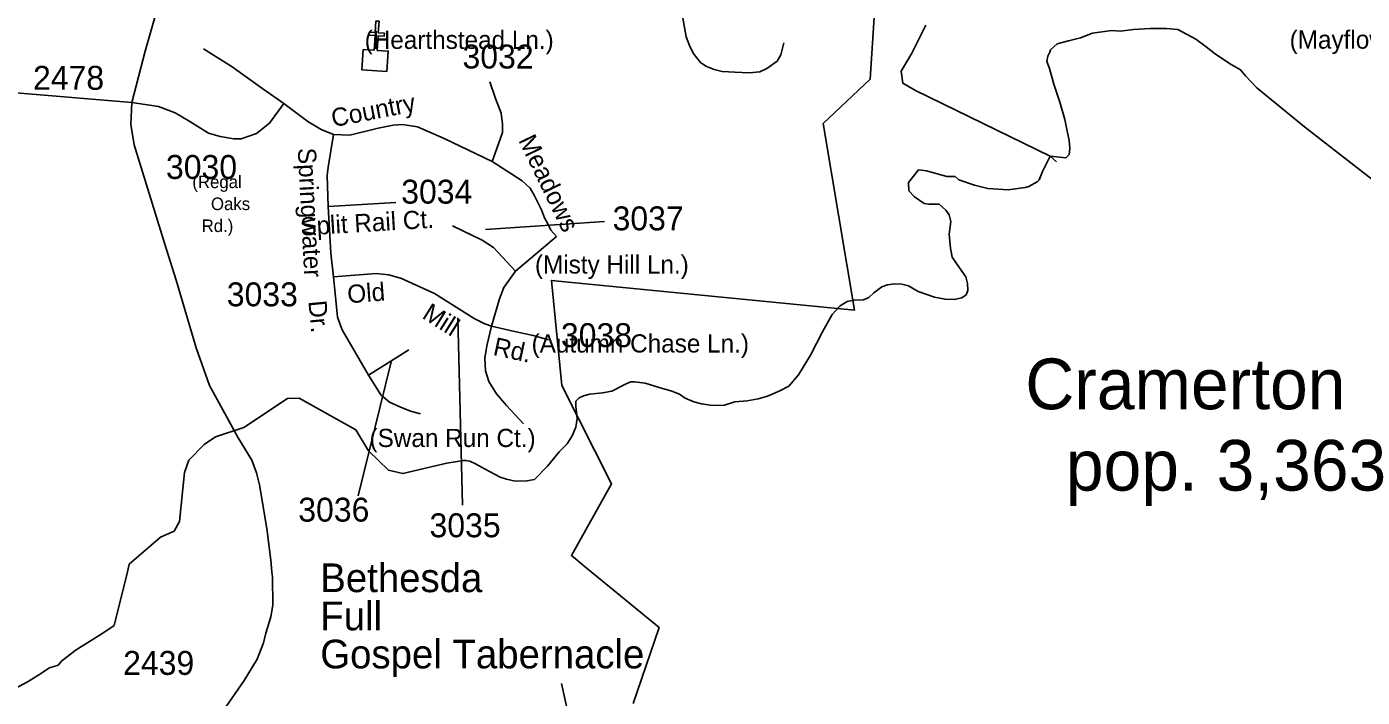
# Model space of a CAD drawing. Extents: x 1364363 to 1407445, y 538563 to 573342.
# Drawn here: x 1372368 to 1379352, y 544821 to 548325 of the extents above; entities that cross this region are included whole.
import ezdxf

# ---------------------------------------------------------------- set-up
doc = ezdxf.new("R2010")
doc.units = 0
for name, color, linetype in [('Exist Boundary Political City Limit New', 7, 'Continuous'), ('Exist Civil Demographics City Label', 7, 'Continuous'), ('Exist Cultural Church CELL', 7, 'Continuous'), ('Exist Cultural Church Label', 7, 'Continuous'), ('Exist Hydrographic Creek Single Shore', 7, 'Continuous'), ('Exist Road Secondary Type 51 Attributed', 7, 'Continuous'), ('Exist Road Secondary Type 51 Label', 7, 'Continuous'), ('Exist Road Secondary Type 51 Number Label', 7, 'Continuous')]:
    doc.layers.add(name, color=color, linetype=linetype)

msp = doc.modelspace()

# ---------------------------------------------------------------- linework, layer by layer
at = {"layer": 'Exist Boundary Political City Limit New'}
msp.add_lwpolyline([(1376807.4, 548482.4), (1376778.2, 548050.8), (1376533.5, 547819.8), (1376697.4, 546843.8), (1375111.8, 546998.8), (1375167.4, 546450.8), (1375426.8, 545936.9), (1375217, 545561.1), (1375280.8, 545506.7), (1375675.1, 545185.3), (1375539.5, 544787.6)], dxfattribs=at)
at = {"layer": 'Exist Cultural Church CELL'}
msp.add_lwpolyline([(1374128.3, 548205.9), (1374185.1, 548202.4), (1374189.9, 548278.4), (1374158, 548280.5), (1374159, 548296.4), (1374190.9, 548294.4), (1374194.7, 548354.4), (1374210.7, 548353.4), (1374206.9, 548293.4), (1374238.8, 548291.4), (1374237.8, 548275.4), (1374205.9, 548277.4), (1374201.1, 548201.4), (1374258.6, 548197.7), (1374251.9, 548091.4), (1374121.6, 548099.7)], close=True, dxfattribs=at)
at = {"layer": 'Exist Hydrographic Creek Single Shore'}
for points in [[(1377720.4, 547647.7), (1377016.1, 547992.2), (1376950.5, 548029.3), (1376941.7, 548093.3), (1376997.2, 548187.2), (1377069.7, 548332.3)], [(1378801.7, 548006), (1378741.9, 548068.8), (1378716.3, 548100.5), (1378666.9, 548127.7), (1378584, 548181.9), (1378536.8, 548220.6), (1378481.6, 548259.5), (1378388.5, 548309.8), (1378326.7, 548315.1), (1378242.5, 548315.2), (1378156.4, 548310.3), (1378086.2, 548301.9), (1378041.2, 548304.7), (1377941.4, 548290.5), (1377878.7, 548267.6), (1377815.9, 548250.5), (1377756, 548236.3), (1377721.8, 548204.9), (1377717.8, 548192), (1377707.3, 548171.7), (1377702.7, 548143.9), (1377716, 548105.9), (1377740.2, 548025), (1377770.4, 547930.8), (1377796.5, 547840), (1377807.5, 547787.3), (1377820.3, 547731.2), (1377823.3, 547689.3), (1377818.7, 547657.4), (1377802.4, 547639.7), (1377720.4, 547647.7), (1377753.9, 547618.5)], [(1380434.5, 545971.1), (1380301.8, 546214), (1380129.4, 546443.2), (1380115.2, 546511.7), (1380004, 546760), (1380006.8, 547065.3), (1379949.8, 547128.1), (1379895.6, 547145.2), (1379050.8, 547801.7), (1378801.7, 548006)], [(1377720.4, 547647.7), (1377680.5, 547567.8), (1377663.3, 547525), (1377666.2, 547527.9), (1377651.9, 547513.6), (1377609.2, 547490.8), (1377589, 547483.9), (1377500.6, 547471.8), (1377394.8, 547479.6), (1377325.2, 547497.5), (1377241.8, 547525.4), (1377223.2, 547542.7), (1377180.6, 547542.7), (1377073.9, 547572.6), (1377031.3, 547576.9), (1376979, 547511.5), (1376981.8, 547467.9), (1377010, 547436), (1377061.1, 547401.9), (1377086.7, 547397.6), (1377139, 547397), (1377174.4, 547366.7), (1377191.8, 547341.7), (1377201, 547306.3), (1377191.8, 547241.7), (1377198.2, 547167.6), (1377207.3, 547121.5), (1377230.6, 547087.4), (1377257.7, 547046.7), (1377279.2, 547018.3), (1377288.4, 546983.7), (1377289.6, 546945.9), (1377281.2, 546923.9), (1377258.9, 546908.8), (1377218.7, 546899.7), (1377170.7, 546900.7), (1377114.8, 546911.7), (1377029.4, 546941.3), (1376980, 546970.2), (1376944.2, 546979.1), (1376906.2, 546981.5), (1376870.1, 546976.5), (1376839.8, 546965.6), (1376797.3, 546934.5), (1376772.7, 546910.4), (1376744.4, 546897), (1376694.4, 546896.4), (1376658.2, 546888.9), (1376621.7, 546865.8), (1376580.8, 546820.6), (1376528.8, 546729.8), (1376466.2, 546608.8), (1376404.1, 546505.8), (1376352.8, 546446.9), (1376306.3, 546421.6), (1376241.7, 546393.4), (1376193.4, 546380.4), (1376135.1, 546369.3), (1376071, 546364.8), (1376016.7, 546347.8), (1375954.5, 546345), (1375896.7, 546354.4), (1375856.9, 546365), (1375811.3, 546384)], [(1375811.3, 546384), (1375781.7, 546405.1), (1375742, 546419.9), (1375676.4, 546439.2), (1375602.8, 546462.9), (1375547, 546469.7), (1375524.8, 546468.6), (1375492.6, 546452.8), (1375427.9, 546420.4), (1375379.6, 546411.6), (1375313.5, 546404.7), (1375279.3, 546395.5), (1375257.1, 546386.1), (1375240.6, 546368.4), (1375240.1, 546339.7), (1375246.8, 546278), (1375239.8, 546232.2), (1375220.9, 546186.6), (1375194, 546145.3), (1375153.2, 546103.5), (1375091.6, 546029.2), (1375024.1, 545958.3)], [(1372552.7, 545010.3), (1372626.8, 545068.1), (1372766.5, 545156.5), (1372826.4, 545196.5), (1372894.8, 545476.1), (1372903.4, 545516.1), (1373067.4, 545657.3), (1373138.7, 545688.7), (1373167.2, 545740.1), (1373192.9, 545996.1), (1373215.7, 546059.7), (1373295.5, 546142.5), (1373355.4, 546182.4), (1373503.7, 546230.9), (1373731.8, 546382.2), (1373793.9, 546384.4), (1374089.9, 546217.6), (1374154.9, 546108), (1374260.9, 546007.4), (1374335.9, 545989.5), (1374564.8, 546043.7), (1374651.8, 546057.7)], [(1375024.1, 545958.3), (1374983.9, 545951), (1374921.9, 545950.6), (1374878, 545959.7), (1374844.2, 545971.8), (1374765, 546013.6), (1374715.6, 546040.9), (1374685.9, 546055.4), (1374663.9, 546057.5), (1374651.8, 546057.7)], [(1372552.7, 545010.3), (1372532.7, 544988.2), (1372487, 544973.9), (1372427.2, 544934), (1372404.3, 544919.7), (1372375.8, 544902.6), (1372284.6, 544854.1)]]:
    msp.add_lwpolyline(points, dxfattribs=at)
at = {"layer": 'Exist Road Secondary Type 51 Attributed'}
for p, q in [((1373945.5, 547385.7), (1374297.7, 547406.8)), ((1374155, 546503.9), (1374366, 546636.3)), ((1375203.1, 544717.6), (1375164.3, 544893.3))]:
    msp.add_line(p, q, dxfattribs=at)
for points in [[(1372917.5, 547929), (1372988.4, 548197.4), (1373112.8, 548637.2), (1373145.3, 548760.6), (1373170.2, 548865.1), (1373194.1, 548979.6), (1373260.6, 549189.9), (1373301.9, 549365.5), (1373340.5, 549476.4), (1373359.1, 549532.3), (1373423, 549729.3), (1373473.5, 549846.5), (1373522.1, 549906.9)], [(1375785, 548447.6), (1375816.8, 548272.3), (1375833.9, 548227.1), (1375854, 548186.5), (1375891.3, 548138.3), (1375919.2, 548118.8), (1375962.6, 548100.7), (1376004.5, 548091.7), (1376071.3, 548087.2), (1376145.7, 548084.1), (1376201.6, 548088.7), (1376238.8, 548106.7), (1376293.1, 548145.8), (1376311.8, 548177.4), (1376327.3, 548240.7)], [(1373712, 547923), (1373603.4, 548001.2), (1373442, 548115.6), (1373293, 548208.9)], [(1374802, 547620.5), (1374835.4, 547712.4), (1374855.6, 547772.5), (1374855.6, 547816.2), (1374849.3, 547873.4), (1374819.9, 547950.1), (1374789.6, 548037.4)], [(1372313.3, 547979.5), (1372917.5, 547929)], [(1373261.2, 544568.6), (1373305.4, 544619.2), (1373505.5, 544909.1), (1373574, 545019.8), (1373605.7, 545105.2), (1373618.7, 545155), (1373645.3, 545241.3), (1373656.1, 545301.5), (1373653, 545447.5), (1373650.6, 545475.6), (1373645.3, 545537.8), (1373623.6, 545701.8), (1373585.3, 545930.5), (1373569.3, 545994.4), (1373546, 546060), (1373474.6, 546175.9), (1373324.8, 546449.7), (1373255, 546646.8), (1373149.5, 547000.5), (1373089, 547194.6), (1372930.7, 547708), (1372912, 547814.5), (1372917.5, 547929)], [(1372917.5, 547929), (1373057.2, 547907.9), (1373144.1, 547874.8), (1373221.7, 547829.7), (1373319.2, 547769.2), (1373380.4, 547750.6), (1373452.2, 547739.9), (1373489.5, 547739.9), (1373569.2, 547766.5), (1373637.5, 547820.7), (1373712, 547923)], [(1373973.4, 547762), (1373907.5, 547787.5), (1373839.2, 547829.7), (1373712, 547923)], [(1373973.4, 547762), (1373945.5, 547590.4), (1373939.3, 547548.3), (1373945.5, 547385.7)], [(1374802, 547620.5), (1374550.6, 547740.9), (1374411, 547801.1), (1374333.4, 547813.1), (1374283.8, 547810.1), (1374206.2, 547795.1), (1374057.2, 547759), (1373973.4, 547762)], [(1375138, 547227.8), (1375108.5, 547262.4), (1375093.7, 547294), (1375075.1, 547325.6), (1375059.6, 547367.7), (1375022.4, 547444.5), (1375000.6, 547480.6), (1374958.7, 547519.7), (1374802, 547620.5)], [(1373945.5, 547385.7), (1373957.9, 547141.9), (1373973.4, 547018.5)], [(1374924.6, 547047.1), (1374809.8, 547170.5), (1374750.8, 547209.7), (1374595.6, 547284.9)], [(1375138, 547227.8), (1375024.7, 547133), (1374924.6, 547047.1)], [(1373973.4, 547018.5), (1374196.1, 547035.1), (1374262.8, 547027.6), (1374328, 547009.5), (1374500.2, 546931.3), (1374708.1, 546800.3), (1374764, 546771.7), (1374798.1, 546759.7)], [(1373973.4, 547018.5), (1373993.6, 546807.9), (1374018.4, 546740.1), (1374155, 546503.9)], [(1374924.6, 547047.1), (1374862.5, 546962.9), (1374840.8, 546902.7), (1374798.1, 546759.7)], [(1374798.1, 546759.7), (1374774.9, 546657.4), (1374764, 546592.7), (1374767.1, 546526.5), (1374785.7, 546470.8), (1374825.3, 546406.1), (1374878.1, 546345.9), (1374966.5, 546249.6)], [(1374798.1, 546759.7), (1374911.4, 546734.2), (1375016.9, 546711.6), (1375097.6, 546689)], [(1374155, 546503.9), (1374220.9, 546401.5), (1374265.9, 546362.4), (1374320.2, 546338.3), (1374374.5, 546315.8), (1374427.3, 546302.2)]]:
    msp.add_lwpolyline(points, dxfattribs=at)
at = {"layer": 'Exist Road Secondary Type 51 Number Label'}
for p, q in [((1374767.4, 547266), (1375389.8, 547306.9)), ((1374622.1, 546803.3), (1374646.6, 545824.7)), ((1374274, 546574), (1374102, 545873.8))]:
    msp.add_line(p, q, dxfattribs=at)

# ---------------------------------------------------------------- texts
at = {"layer": 'Exist Civil Demographics City Label'}
for s, p in [('Cramerton', (1377590.2, 546325.9)), ('pop. 3,363', (1377802.4, 545900.6))]:
    msp.add_text(s, height=265, dxfattribs=at).set_placement(p)
at = {"layer": 'Exist Cultural Church Label'}
for s, p in [('Bethesda ', (1373903.4, 545370.1)), ('Full', (1373903.4, 545170.8)), ('Gospel Tabernacle', (1373903.4, 544971.6))]:
    msp.add_text(s, height=150, dxfattribs=at).set_placement(p)
at = {"layer": 'Exist Road Secondary Type 51 Label'}
for s, height, p in [('(Hearthstead Ln.)', 95, (1374135.6, 548208.9)), ('(Mayflower St.)', 95, (1378972.5, 548210.3)), ('(Regal ', 65.62, (1373234.3, 547481.5)), ('    Oaks ', 65.62, (1373234.3, 547366.7)), ('  Rd.)', 65.62, (1373234.3, 547251.9)), ('(Misty Hill Ln.)', 95, (1375025.9, 547034.9)), ('(Autumn Chase Ln.)', 95, (1375008.4, 546622.4)), ('(Swan Run Ct.)', 95, (1374161.1, 546128.5))]:
    msp.add_text(s, height=height, dxfattribs=at).set_placement(p)
for s, rotation, p in [('Country', 10.97779, (1373970.9, 547799.6)), ('Meadows', 295.88311, (1374937.6, 547731.9)), ('Springwater', 272.91477, (1373785.6, 547689.8)), ('Split Rail Ct.', 3.42302, (1373802.2, 547232.7)), ('Old', 4.25198, (1374048.2, 546879.5)), ('Dr.', 275.46917, (1373840.8, 546890.4)), ('Mill', 327.80161, (1374430.3, 546804.9)), ('Rd.', 347.92386, (1374802.5, 546610))]:
    msp.add_text(s, height=95, rotation=rotation, dxfattribs=at).set_placement(p)
at = {"layer": 'Exist Road Secondary Type 51 Number Label'}
for s, p in [('3032', (1374647.1, 548106.6)), ('2478', (1372401.3, 547995.4)), ('3030', (1373096.5, 547529.5)), ('3034', (1374326.7, 547400.4)), ('3037', (1375431.9, 547260.9)), ('3033', (1373414.6, 546863.8)), ('3038', (1375161.8, 546650.6)), ('3036', (1373788.3, 545738.6)), ('3035', (1374474.7, 545656.9)), ('2439', (1372872.5, 544937.7))]:
    msp.add_text(s, height=125, dxfattribs=at).set_placement(p)

doc.saveas('drawing.dxf')
